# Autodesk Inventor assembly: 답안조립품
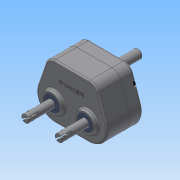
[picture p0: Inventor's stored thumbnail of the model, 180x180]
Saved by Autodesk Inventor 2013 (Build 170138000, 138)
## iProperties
Created: 2014-12
Part Number: 답안조립품
Document SubType Name: Assembly
Designer: Administrator
Author: Administrator
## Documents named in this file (14)
- C:\Users\Administrator\Desktop\441209V1042\441209V1042\답안조립품.iam
- C:\Users\Administrator\Desktop\441209V1042\441209V1042\본체.ipt
- C:\Users\Administrator\Desktop\441209V1042\441209V1042\M 5 x 35.ipt
- C:\Users\Administrator\Desktop\441209V1042\441209V1042\멈춤링.ipt
- C:\Users\Administrator\Desktop\441209V1042\441209V1042\메인기어.ipt
- C:\Users\Administrator\Desktop\441209V1042\441209V1042\메인축.ipt
- C:\Users\Administrator\Desktop\441209V1042\441209V1042\베어링- 6202.ipt
- C:\Users\Administrator\Desktop\441209V1042\441209V1042\베어링- 6203.ipt
- C:\Users\Administrator\Desktop\441209V1042\441209V1042\서브기어.ipt
- C:\Users\Administrator\Desktop\441209V1042\441209V1042\서브축.ipt
- C:\Users\Administrator\Desktop\441209V1042\441209V1042\오일시일-D-15.ipt
- C:\Users\Administrator\Desktop\441209V1042\441209V1042\오일시일-D-17.ipt
- C:\Users\Administrator\Desktop\441209V1042\441209V1042\커버.ipt
- C:\Users\Administrator\Desktop\441209V1042\441209V1042\키5x5.ipt
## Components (15 placed, 6 different names)
1. KS B 1003 - 미터 M 5 x 35:1
2. KS B 1336 17 x 1:1
3. KS B 2023 6202 - 15 x 35 x 11:1
4. KS B 2023 6203 - 17 x 40 x 12:1
5. KS B 2804 D D - 15 30 7:1 — 플러쉬:1
6. KS B 2804 D D - 17 30 8:1 — 플러쉬:2
7. KS B 2023 6203 - 17 x 40 x 12:2
8. KS B 2023 6203 - 17 x 40 x 12:3
9. KS B 2023 6203 - 17 x 40 x 12:4
10. KS B 1003 - 미터 M 5 x 35:2
11. KS B 1003 - 미터 M 5 x 35:3
12. KS B 2023 6202 - 15 x 35 x 11:2
13. KS B 1336 17 x 1:2
14. KS B 1336 17 x 1:3
15. KS B 2804 D D - 15 30 7:2 — 플러쉬:3
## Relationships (3: Flush 3)
- 플러쉬:1 [Flush]: KS B 2804 D D - 15 30 7:1
- 플러쉬:2 [Flush]: KS B 2804 D D - 17 30 8:1
- 플러쉬:3 [Flush]: KS B 2804 D D - 15 30 7:2
